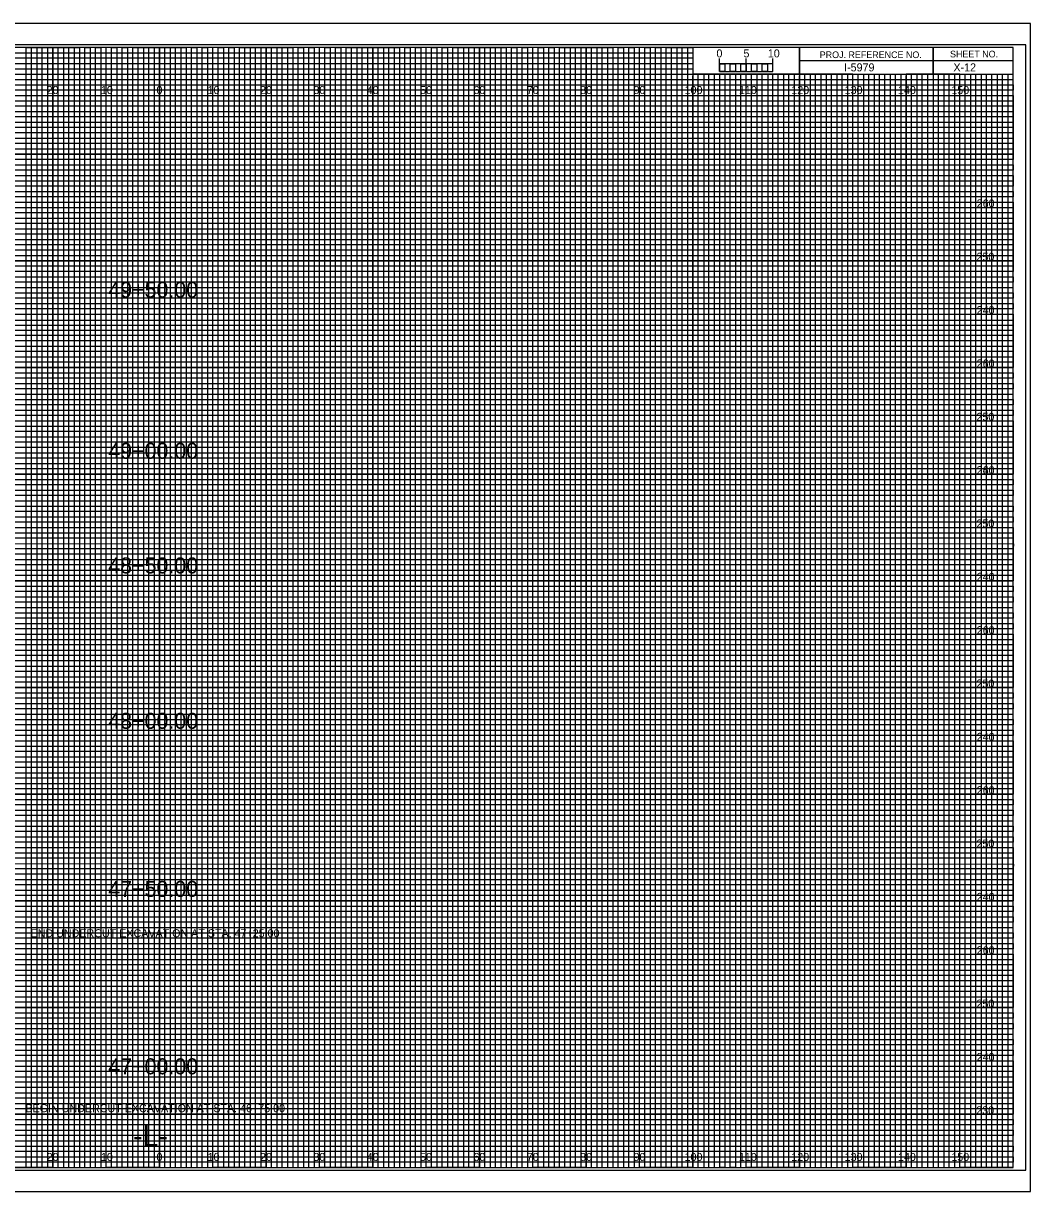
# Model space of a CAD drawing. Extents: x -13 to 359, y -5 to 2854.
# Drawn here: x 134.5 to 323.3, y 2415.5 to 2634.5 of the extents above; entities that cross this region are included whole.
import ezdxf

# ---------------------------------------------------------------- set-up
doc = ezdxf.new("R2010")
doc.units = 0
for name, color, linetype in [('Exist CMT Pavement', 7, 'Continuous'), ('Exist Cross Section Cell', 7, 'Continuous'), ('Exist XS Ground Line', 7, 'Continuous'), ('Prop CMT Conc Surface', 7, 'Continuous'), ('Prop CMT Concrete Structures', 7, 'Continuous'), ('Prop CMT DNC', 7, 'Continuous'), ('Prop CMT Pvmt Course 1', 7, 'Continuous'), ('Prop CMT Pvmt Course 1 CG', 7, 'Continuous'), ('Prop CMT Pvmt Course 1 Wedge', 7, 'Continuous'), ('Prop CMT Pvmt Course 2', 7, 'Continuous'), ('Prop CMT Pvmt Course 2 Wedge', 7, 'Continuous'), ('Prop CMT Pvmt Course 3', 7, 'Continuous'), ('Prop CMT Pvmt Course 3 Wedge', 7, 'Continuous'), ('Prop CMT Pvmt Wedge Surface 2', 7, 'Continuous'), ('Prop CMT Shear Line', 7, 'Continuous'), ('Prop CMT Slope Grass', 7, 'Continuous'), ('Prop CMT Subgrade Earthwork', 7, 'Continuous'), ('Scratch_Level_0', 7, 'Continuous')]:
    doc.layers.add(name, color=color, linetype=linetype)

msp = doc.modelspace()

# ---------------------------------------------------------------- linework, layer by layer
at = {"layer": 'Exist XS Ground Line'}
for p, q in [((150, 2630), (140, 2630)), ((140, 2630), (140, 2420)), ((150, 2420), (150, 2630)), ((170, 2630), (160, 2630)), ((160, 2630), (160, 2420)), ((170, 2420), (170, 2630)), ((190, 2630), (180, 2630)), ((180, 2630), (180, 2420)), ((190, 2420), (190, 2630)), ((210, 2630), (200, 2630)), ((200, 2630), (200, 2420)), ((210, 2420), (210, 2630)), ((230, 2630), (220, 2630)), ((220, 2630), (220, 2420)), ((230, 2420), (230, 2630)), ((250, 2630), (240, 2630)), ((240, 2630), (240, 2420)), ((250, 2420), (250, 2630)), ((260, 2630), (260, 2420)), ((270, 2420), (270, 2625)), ((290, 2625), (280, 2625)), ((280, 2625), (280, 2420)), ((290, 2420), (290, 2625)), ((310, 2625), (300, 2625)), ((300, 2625), (300, 2420)), ((310, 2420), (310, 2625)), ((140, 2420), (130, 2420)), ((160, 2420), (150, 2420)), ((180, 2420), (170, 2420)), ((200, 2420), (190, 2420)), ((220, 2420), (210, 2420)), ((240, 2420), (230, 2420)), ((260, 2420), (250, 2420)), ((280, 2420), (270, 2420)), ((300, 2420), (290, 2420)), ((320, 2420), (310, 2420)), ((320, 2420), (320, 2420))]:
    msp.add_line(p, q, dxfattribs=at)
for points in [[(0, 2620), (320, 2620), (320, 2610), (0, 2610)], [(0, 2600), (320, 2600), (320, 2590), (0, 2590)], [(0, 2580), (320, 2580), (320, 2570), (0, 2570)], [(0, 2560), (320, 2560), (320, 2550), (0, 2550)], [(0, 2540), (320, 2540), (320, 2530), (0, 2530)], [(0, 2520), (320, 2520), (320, 2510), (0, 2510)], [(0, 2500), (320, 2500), (320, 2490), (0, 2490)], [(0, 2480), (320, 2480), (320, 2470), (0, 2470)], [(0, 2460), (320, 2460), (320, 2450), (0, 2450)], [(0, 2440), (320, 2440), (320, 2430), (0, 2430)]]:
    msp.add_lwpolyline(points, dxfattribs=at)
at = {"layer": 'Prop CMT Conc Surface'}
for p, q in [((265, 2625.49), (265, 2627.9)), ((265, 2626.9), (265, 2627.9)), ((270, 2625.49), (270, 2627.9)), ((275, 2625.49), (275, 2627.9)), ((275, 2626.9), (275, 2627.9))]:
    msp.add_line(p, q, dxfattribs=at)
for points in [[(275, 2626.9), (265, 2626.9), (265, 2625.49), (275, 2625.49)], [(265, 2626.9), (266, 2626.9), (266, 2625.49), (265, 2625.49)], [(267, 2626.9), (268, 2626.9), (268, 2625.49), (267, 2625.49)], [(269, 2626.9), (270, 2626.9), (270, 2625.49), (269, 2625.49)], [(271, 2626.9), (272, 2626.9), (272, 2625.49), (271, 2625.49)], [(273, 2626.9), (274, 2626.9), (274, 2625.49), (273, 2625.49)]]:
    msp.add_lwpolyline(points, close=True, dxfattribs=at)
at = {"layer": 'Prop CMT Concrete Structures'}
for p, q in [((305, 2630), (305, 2625)), ((305, 2625), (305, 2630)), ((280, 2627.5), (280, 2625)), ((320, 2627.49), (280, 2627.49)), ((280, 2625), (320, 2625))]:
    msp.add_line(p, q, dxfattribs=at)
for points in [[(320, 2630), (0, 2630), (0, 2420), (320, 2420)], [(280, 2630), (260, 2630), (260, 2625.03), (280, 2625.03)], [(320, 2630), (280, 2630), (280, 2625), (320, 2625)]]:
    msp.add_lwpolyline(points, close=True, dxfattribs=at)
at = {"layer": 'Prop CMT DNC'}
for p, q in [((323.3, 2634.5), (-13.4, 2634.5)), ((-13.4, 2415.5), (323.3, 2415.5))]:
    msp.add_line(p, q, dxfattribs=at)
at = {"layer": 'Prop CMT Pvmt Course 1'}
for p, q in [((0, 2629), (260, 2629)), ((260, 2629), (260, 2627.98)), ((260, 2627.98), (0, 2627.98)), ((0, 2627), (260, 2627)), ((260, 2625.89), (0, 2625.89)), ((260, 2627), (260, 2625.89)), ((0, 2624), (320, 2624))]:
    msp.add_line(p, q, dxfattribs=at)
for points in [[(0, 2623), (270, 2623), (320, 2623), (320, 2622), (0, 2622)], [(0, 2621), (320, 2621), (320, 2619), (0, 2619)], [(0, 2618), (320, 2618), (320, 2617), (0, 2616.98)], [(0, 2616), (320, 2616), (320, 2614), (0, 2614)], [(0, 2613), (320, 2613), (320, 2612), (0, 2612)], [(0, 2611), (320, 2611), (320, 2609), (0, 2609)], [(0, 2608), (320, 2608), (320, 2607), (0, 2607)], [(0, 2606), (320, 2606), (320, 2604), (0, 2604)], [(0, 2603), (320, 2603), (320, 2602), (0, 2602)], [(0, 2601), (320, 2601), (320, 2599), (0, 2599)], [(0, 2598), (320, 2598), (320, 2597), (0, 2597)], [(0, 2596), (320, 2596), (320, 2593.95), (320, 2593), (320, 2592), (0, 2592)], [(0, 2594), (320, 2594), (320, 2593), (0, 2593)], [(0, 2591), (320, 2591), (320, 2589), (0, 2589.03)], [(0, 2589.03), (320, 2589), (320, 2588), (0, 2588)], [(0, 2587), (320, 2587), (320, 2586), (0, 2586)], [(0, 2584), (320, 2584), (320, 2583), (0, 2583)], [(0, 2582), (320, 2582), (320, 2581), (0, 2581)], [(-0.07, 2578.89), (320, 2578.89), (320, 2577.88), (-0.07, 2577.88)], [(0, 2577), (320, 2577), (320, 2576), (0, 2576)], [(0, 2574), (320, 2574), (320, 2573), (0, 2573)], [(0, 2572), (320, 2572), (320, 2571), (0, 2571)], [(0, 2569), (320, 2569), (320, 2568), (0, 2568)], [(0, 2567), (320, 2567), (320, 2566), (0, 2566)], [(0, 2564), (320, 2564), (320, 2563), (0, 2563)], [(0, 2562), (320, 2562), (320, 2561), (0, 2561)], [(0, 2559), (320, 2559), (319.99, 2557.98), (0, 2558)], [(0, 2557), (320, 2557), (320, 2556), (0, 2556)], [(0, 2554), (320, 2554), (320, 2553), (0, 2553)], [(0, 2552), (320, 2552), (320, 2551), (0, 2551)], [(0, 2549), (320, 2549), (320, 2548), (0, 2548)], [(0, 2547), (320, 2547), (320, 2546), (0, 2546)], [(0, 2544), (320, 2544), (320, 2543), (0, 2543)], [(0, 2542), (320, 2542), (320, 2541), (0, 2541)], [(0, 2539), (320, 2539), (320, 2538), (0, 2538)], [(0, 2536.99), (320.07, 2536.91), (320, 2536), (0, 2536)], [(0, 2534), (320, 2534), (320, 2533), (0, 2533)], [(0, 2532), (320, 2532), (320, 2531), (0, 2531)], [(0, 2529), (320, 2529), (320, 2528), (0, 2528)], [(0, 2527), (320, 2527), (320, 2526), (0, 2526)], [(0, 2524), (320, 2524), (320, 2523), (0, 2523)], [(0, 2522), (320, 2522), (320, 2521), (0, 2521)], [(0, 2519), (320, 2519), (320, 2518), (0, 2518)], [(0, 2517), (320, 2517), (320, 2516), (0, 2516)], [(0, 2514), (320, 2514), (320, 2513), (0, 2513)], [(0, 2512), (320, 2512), (320, 2511), (0, 2511)], [(0, 2509), (320, 2509), (320, 2508), (0, 2508)], [(0, 2507), (320, 2507), (320, 2506), (0, 2506)], [(0, 2504), (320, 2504), (320, 2503), (0, 2503)], [(0, 2502), (320, 2502), (320, 2501), (0, 2501)], [(0, 2499), (320, 2499), (319.99, 2497.98), (0, 2498)], [(0, 2497), (320, 2497), (320, 2496), (0, 2496)], [(0, 2494), (320, 2494), (320, 2493), (0, 2493)], [(0, 2492), (320, 2492), (320, 2491), (0, 2491)], [(0, 2489), (320, 2489), (320, 2488), (0, 2488)], [(0, 2487), (320, 2487), (320, 2486), (0, 2486)], [(0, 2484), (320, 2484), (320, 2483), (0, 2483)], [(0, 2482), (320, 2482), (320, 2481), (0, 2481)], [(0, 2479), (320, 2479), (320, 2478), (0, 2478)], [(0, 2476.99), (320.07, 2476.91), (320, 2476), (0, 2476)], [(0, 2474), (320, 2474), (320, 2473), (0, 2473)], [(0, 2472), (320, 2472), (320, 2471), (0, 2471)], [(0, 2469), (320, 2469), (320, 2468), (0, 2468)], [(0, 2467), (320, 2467), (320, 2466), (0, 2466)], [(0, 2464), (320, 2464), (320, 2463), (0, 2463)], [(0, 2462), (320, 2462), (320, 2461), (0, 2461)], [(0, 2459), (320, 2459), (320, 2458), (0, 2458)], [(0, 2457), (320, 2457), (320, 2456), (0, 2456)], [(0, 2454), (320, 2454), (320, 2453), (0, 2453)], [(0, 2452), (320, 2452), (320, 2451), (0, 2451)], [(0, 2449), (320, 2449), (320, 2448), (0, 2448)], [(0, 2447), (320, 2447), (320, 2446), (0, 2446)], [(0, 2444), (320, 2444), (320, 2443), (0, 2443)], [(0, 2442), (320, 2442), (320, 2441), (0, 2441)], [(0, 2439), (320, 2439), (320, 2438), (0, 2438)], [(0, 2437), (320, 2437), (320, 2436), (0, 2436)], [(0, 2434), (320, 2434), (320, 2433), (0, 2433)], [(0, 2432), (320, 2432), (320, 2431), (0, 2431)], [(0, 2429), (320, 2429), (320, 2428), (0, 2428)], [(0, 2427), (320, 2427), (320, 2426), (0, 2426)], [(0, 2424), (320, 2424), (320, 2423), (0, 2423)], [(0, 2422), (320, 2422), (320, 2421), (0, 2421)]]:
    msp.add_lwpolyline(points, dxfattribs=at)
at = {"layer": 'Prop CMT Pvmt Course 1 CG'}
for p, q in [((267, 2625), (266.01, 2625)), ((266.01, 2625), (266.01, 2420)), ((267, 2420), (267, 2625)), ((269, 2625), (268, 2625)), ((268, 2625), (268, 2420)), ((269, 2420), (269, 2625)), ((266.01, 2420), (265, 2420)), ((268, 2420), (267, 2420))]:
    msp.add_line(p, q, dxfattribs=at)
for points in [[(135, 2420), (136, 2420), (136, 2630), (137, 2630), (137, 2420)], [(137, 2420), (138, 2420), (138, 2630), (139, 2630), (139, 2420)], [(140, 2420), (141, 2420), (141, 2630), (142, 2630), (142, 2420)], [(142, 2420), (143, 2420), (143, 2630), (144, 2630), (144, 2420)], [(145, 2420), (146, 2420), (146, 2630), (147, 2630), (147, 2420)], [(147, 2420), (148, 2420), (148, 2630), (149, 2630), (149, 2420)], [(150, 2420), (151, 2420), (151, 2630), (152, 2630), (152, 2420)], [(152, 2420), (153, 2420), (153, 2630), (154, 2630), (154, 2420)], [(155, 2420), (156, 2420), (156, 2630), (157, 2630), (157, 2420)], [(157, 2420), (158, 2420), (158, 2630), (159, 2630), (159, 2420)], [(160, 2420), (161, 2420), (161, 2630), (162, 2630), (162, 2420)], [(162, 2420), (163, 2420), (163, 2630), (164, 2630), (164, 2420)], [(165, 2420), (166, 2420), (166, 2630), (167, 2630), (167, 2420)], [(167, 2420), (168, 2420), (168, 2630), (169, 2630), (169, 2420)], [(170, 2420), (171, 2420), (171, 2630), (172, 2630), (172, 2420)], [(172, 2420), (173, 2420), (173, 2630), (174, 2630), (174, 2420)], [(175, 2420), (176, 2420), (176, 2630), (177, 2630), (177, 2420)], [(177, 2420), (178, 2420), (178, 2630), (179, 2630), (179, 2420)], [(180, 2420), (181, 2420), (181, 2630), (182, 2630), (182, 2420)], [(182, 2420), (183, 2420), (183, 2630), (184, 2630), (184, 2420)], [(185, 2420), (186, 2420), (186, 2630), (187, 2630), (187, 2420)], [(187, 2420), (188, 2420), (188, 2630), (189, 2630), (189, 2420)], [(190, 2420), (191, 2420), (191, 2630), (192, 2630), (192, 2420)], [(192, 2420), (193, 2420), (193, 2630), (194, 2630), (194, 2420)], [(195, 2420), (196, 2420), (196, 2630), (197, 2630), (197, 2420)], [(197, 2420), (198, 2420), (198, 2630), (199, 2630), (199, 2420)], [(200, 2420), (201, 2420), (201, 2630), (202, 2630), (202, 2420)], [(202, 2420), (203, 2420), (203, 2630), (204, 2630), (204, 2420)], [(205, 2420), (206, 2420), (206, 2630), (207, 2630), (207, 2420)], [(207, 2420), (208, 2420), (208, 2630), (209, 2630), (209, 2420)], [(210, 2420), (211, 2420), (211, 2630), (212, 2630), (212, 2420)], [(212, 2420), (213, 2420), (213, 2630), (214, 2630), (214, 2420)], [(215, 2420), (216, 2420), (216, 2630), (217, 2630), (217, 2420)], [(217, 2420), (218, 2420), (218, 2630), (219, 2630), (219, 2420)], [(220, 2420), (221, 2420), (221, 2630), (222, 2630), (222, 2420)], [(222, 2420), (223, 2420), (223, 2630), (224, 2630), (224, 2420)], [(225, 2420), (226, 2420), (226, 2630), (227, 2630), (227, 2420)], [(227, 2420), (228, 2420), (228, 2630), (229, 2630), (229, 2420)], [(230, 2420), (231, 2420), (231, 2630), (232, 2630), (232, 2420)], [(232, 2420), (233, 2420), (233, 2630), (234, 2630), (234, 2420)], [(235, 2420), (236, 2420), (236, 2630), (237, 2630), (237, 2420)], [(237, 2420), (238, 2420), (238, 2630), (239, 2630), (239, 2420)], [(240, 2420), (241, 2420), (241, 2630), (242, 2630), (242, 2420)], [(242, 2420), (243, 2420), (243, 2630), (244, 2630), (244, 2420)], [(245, 2420), (246, 2420), (246, 2630), (247, 2630), (247, 2420)], [(247, 2420), (248, 2420), (248, 2630), (249, 2630), (249, 2420)], [(250, 2420), (251, 2420), (251, 2630), (252, 2630), (252, 2420)], [(252, 2420), (253, 2420), (253, 2630), (254, 2630), (254, 2420)], [(255, 2420), (256, 2420), (256, 2630), (257, 2630), (257, 2420)], [(257, 2420), (258, 2420), (258, 2630), (259, 2630), (259, 2420)], [(260, 2420), (261, 2420), (261, 2625), (262.02, 2625), (262.02, 2420)], [(262, 2420), (263, 2420), (263, 2625), (263.99, 2625), (263.99, 2420)], [(270, 2420), (270.98, 2420), (270.98, 2625), (272, 2625), (272, 2420)], [(272, 2420), (273, 2420), (273, 2625), (274.05, 2625), (274.05, 2420)], [(275, 2420), (276, 2420), (276, 2625), (277, 2625), (277, 2420)], [(277, 2420), (278, 2420), (278, 2625), (279, 2625), (279, 2420)], [(280, 2420), (281, 2420), (281, 2625), (282, 2625), (282, 2420)], [(282, 2420), (283, 2420), (283, 2625), (284, 2625), (284, 2420)], [(285, 2420), (286, 2420), (286, 2625), (287, 2625), (287, 2420)], [(287, 2420), (288, 2420), (288, 2625), (289, 2625), (289, 2420)], [(290, 2420), (291, 2420), (291, 2625), (292, 2625), (292, 2420)], [(292, 2420), (293, 2420), (293, 2625), (294, 2625), (294, 2420)], [(295, 2420), (296, 2420), (296, 2625), (297, 2625), (297, 2420)], [(297, 2420), (298, 2420), (298, 2625), (299, 2625), (299, 2420)], [(300, 2420), (301, 2420), (301, 2625), (302, 2625), (302, 2420)], [(302, 2420), (303, 2420), (303, 2625), (304, 2625), (304, 2420)], [(305, 2420), (306, 2420), (306, 2625), (307, 2625), (307, 2420)], [(307, 2420), (308, 2420), (308, 2625), (309, 2625), (309, 2420)], [(310, 2420), (311, 2420), (311, 2625), (312, 2625), (312, 2420)], [(312, 2420), (313, 2420), (313, 2625), (314, 2625), (314, 2420)], [(315, 2420), (316, 2420), (316, 2625), (317, 2625), (317, 2420)], [(317, 2420), (318, 2420), (318, 2625), (319, 2625), (319, 2420)]]:
    msp.add_lwpolyline(points, dxfattribs=at)
at = {"layer": 'Prop CMT Shear Line'}
for p, q in [((140, 2420), (140, 2630)), ((150, 2420), (150, 2630)), ((160, 2420), (160, 2630)), ((170, 2420), (170, 2630)), ((180, 2420), (180, 2630)), ((190, 2420), (190, 2630)), ((200, 2420), (200, 2630)), ((210, 2420), (210, 2630)), ((220, 2420), (220, 2630)), ((230, 2420), (230, 2630)), ((240, 2420), (240, 2630)), ((250, 2420), (250, 2630)), ((260, 2420), (260, 2624.69)), ((270, 2420), (270, 2624.69)), ((280, 2420), (280, 2624.69)), ((290, 2420), (290, 2624.69)), ((300, 2420), (300, 2624.69)), ((310, 2420), (310, 2624.69)), ((0, 2620), (320, 2620)), ((0, 2610), (320, 2610)), ((0, 2600), (320, 2600)), ((0, 2590), (320, 2590)), ((0, 2580), (320, 2580)), ((0, 2570), (320, 2570)), ((0, 2560), (320, 2560)), ((0, 2550), (320, 2550)), ((0, 2540), (320, 2540)), ((0, 2530), (320, 2530)), ((0, 2520), (320, 2520)), ((0, 2510), (320, 2510)), ((0, 2500), (320, 2500)), ((0, 2490), (320, 2490)), ((0, 2480), (320, 2480)), ((0, 2470), (320, 2470)), ((0, 2460), (320, 2460)), ((0, 2450), (320, 2450)), ((0, 2440), (320, 2440)), ((0, 2430), (320, 2430))]:
    msp.add_line(p, q, dxfattribs=at)
at = {"layer": 'Prop CMT Slope Grass'}
msp.add_lwpolyline([(-10.8, 2419.5), (322.4, 2419.5), (322.4, 2630.5), (-10.8, 2630.5)], close=True, dxfattribs=at)
at = {"layer": 'Prop CMT Subgrade Earthwork'}
msp.add_lwpolyline([(-13.4, 2415.5), (323.3, 2415.5), (323.3, 2634.5), (-13.4, 2634.5)], close=True, dxfattribs=at)
at = {"layer": 'Scratch_Level_0'}
for points in [[(125, 2420), (135, 2420), (135, 2630), (145, 2630), (145, 2420), (155, 2420), (155, 2630), (165, 2630), (165, 2420), (175, 2420), (175, 2630), (185, 2630), (185, 2420), (195, 2420), (195, 2630), (205, 2630), (205, 2420), (215, 2420), (215, 2630), (225, 2630), (225, 2420), (235, 2420), (235, 2630), (245, 2630), (245, 2420), (255, 2420), (255, 2630), (259.93, 2630), (260, 2630), (260, 2625), (264.99, 2625), (264.99, 2420), (275, 2420), (275, 2625), (285, 2625), (285, 2420), (295, 2420), (295, 2625), (305, 2625), (305, 2420), (315, 2420), (315, 2625)], [(0, 2625), (275, 2625)], [(0, 2605), (320, 2605), (320, 2615), (0, 2615)], [(0, 2585), (320, 2585), (320, 2595), (0, 2595)], [(0, 2565), (320, 2565), (320, 2575), (0, 2575)], [(0, 2545), (320, 2545), (320, 2555), (0, 2555)], [(0, 2525), (320, 2525), (320, 2535), (0, 2535)], [(0, 2505), (320, 2505), (320, 2515), (0, 2515)], [(0, 2485), (320, 2485), (320, 2495), (0, 2495)], [(0, 2465), (320, 2465), (320, 2475), (0, 2475)], [(0, 2445), (320, 2445), (320, 2455), (0, 2455)], [(0, 2425), (320, 2425), (320, 2435), (0, 2435)]]:
    msp.add_lwpolyline(points, dxfattribs=at)

# ---------------------------------------------------------------- texts
at = {"layer": 'Exist CMT Pavement'}
for s, p in [('5', (269.47, 2628.12)), ('10', (274.04, 2628.12))]:
    msp.add_text(s, height=1.5, dxfattribs=at).set_placement(p)
at = {"layer": 'Exist Cross Section Cell'}
for s, p in [('20', (138.86, 2621.25)), ('10', (149.04, 2621.25)), ('0', (159.45, 2621.25)), ('0', (159.45, 2621.25)), ('10', (169.04, 2621.25)), ('20', (178.86, 2621.25)), ('30', (188.86, 2621.25)), ('40', (198.86, 2621.25)), ('50', (208.86, 2621.25)), ('60', (218.86, 2621.25)), ('70', (228.86, 2621.25)), ('80', (238.86, 2621.25)), ('90', (248.86, 2621.25)), ('100', (258.44, 2621.25)), ('110', (268.62, 2621.25)), ('120', (278.44, 2621.25)), ('130', (288.44, 2621.25)), ('140', (298.44, 2621.25)), ('150', (308.44, 2621.25)), ('20', (138.86, 2421.25)), ('10', (149.04, 2421.25)), ('0', (159.45, 2421.25)), ('0', (159.45, 2421.25)), ('10', (169.04, 2421.25)), ('20', (178.86, 2421.25)), ('30', (188.86, 2421.25)), ('40', (198.86, 2421.25)), ('50', (208.86, 2421.25)), ('60', (218.86, 2421.25)), ('70', (228.86, 2421.25)), ('80', (238.86, 2421.25)), ('90', (248.86, 2421.25)), ('100', (258.44, 2421.25)), ('110', (268.62, 2421.25)), ('120', (278.44, 2421.25)), ('130', (288.44, 2421.25)), ('140', (298.44, 2421.25)), ('150', (308.44, 2421.25))]:
    msp.add_text(s, height=1.5, dxfattribs=at).set_placement(p)
at = {"layer": 'Prop CMT Conc Surface'}
msp.add_text('0', height=1.5, dxfattribs=at).set_placement((264.41, 2628.12))
at = {"layer": 'Prop CMT Concrete Structures'}
for s, p in [('PROJ. REFERENCE NO.', (283.77, 2627.99)), ('SHEET NO.', (308.19, 2628.12))]:
    msp.add_text(s, height=1.25, dxfattribs=at).set_placement(p)
at = {"layer": 'Prop CMT Pvmt Course 1 Wedge'}
msp.add_text('X-12', height=1.5, dxfattribs=at).set_placement((308.83, 2625.5))
at = {"layer": 'Prop CMT Pvmt Course 2'}
for s, p in [('260', (313.19, 2600)), ('250', (313.15, 2590)), ('240', (313.19, 2580)), ('260', (313.19, 2570)), ('250', (313.15, 2560)), ('260', (313.19, 2550)), ('240', (313.19, 2550)), ('250', (313.15, 2540)), ('240', (313.19, 2530)), ('260', (313.19, 2520)), ('250', (313.15, 2510)), ('240', (313.19, 2500)), ('260', (313.19, 2490)), ('250', (313.15, 2480)), ('240', (313.19, 2470)), ('260', (313.19, 2460)), ('250', (313.15, 2450)), ('240', (313.19, 2440)), ('230', (313.11, 2430))]:
    msp.add_text(s, height=1.5, dxfattribs=at).set_placement(p)
at = {"layer": 'Prop CMT Pvmt Course 2 Wedge'}
msp.add_text('I-5979', height=1.5, dxfattribs=at).set_placement((288.34, 2625.5))
at = {"layer": 'Prop CMT Pvmt Course 3'}
for s, p in [('49+50.00', (150.41, 2583.07)), ('49+00.00', (150.41, 2552.88)), ('48+50.00', (150.41, 2531.39)), ('48+00.00', (150.41, 2502.26)), ('47+50.00', (150.41, 2470.75)), ('47+00.00', (150.41, 2437.49))]:
    msp.add_text(s, height=3, dxfattribs=at).set_placement(p)
at = {"layer": 'Prop CMT Pvmt Course 3 Wedge'}
msp.add_text('-L-', height=4, dxfattribs=at).set_placement((155.06, 2424))
at = {"layer": 'Prop CMT Pvmt Wedge Surface 2'}
for s, p in [('END UNDERCUT EXCAVATION AT STA. 47+25.00', (135.86, 2463.19)), ('BEGIN UNDERCUT EXCAVATION AT STA. 46+75.00', (134.89, 2430.39))]:
    msp.add_text(s, height=1.5, dxfattribs=at).set_placement(p)

doc.saveas('drawing.dxf')
